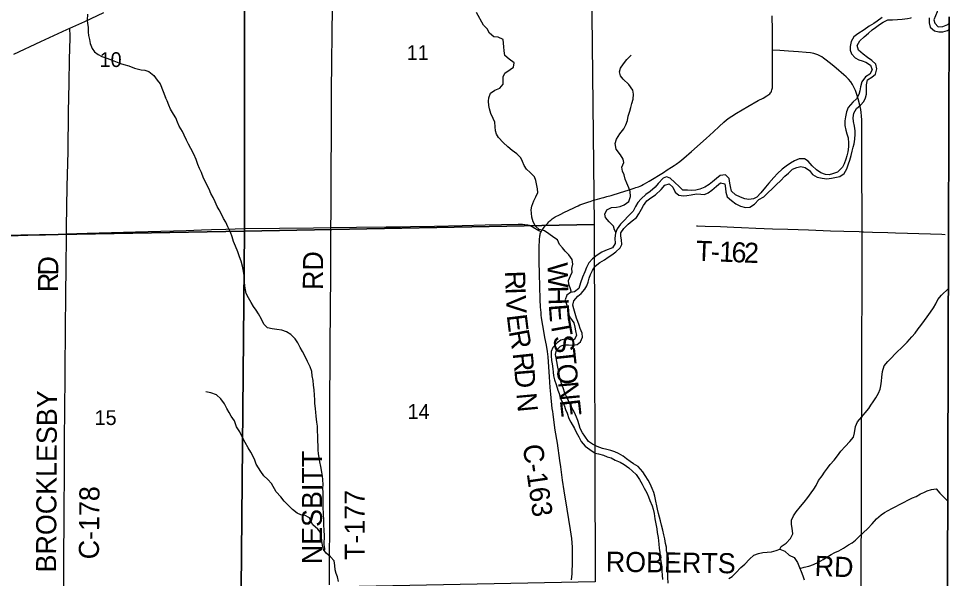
# Model space of a CAD drawing. Extents: x 1584893 to 1934202, y 663575 to 1091909.
# Drawn here: x 1827514 to 1841405, y 948099 to 956462 of the extents above; entities that cross this region are included whole.
import ezdxf

# ---------------------------------------------------------------- set-up
doc = ezdxf.new("R2010")
doc.units = 0
for name, color, linetype in [('GM_X_Adjacent_County', 7, 'Continuous'), ('GM_X_County', 7, 'Continuous'), ('GM_X_County_Road', 7, 'Continuous'), ('GM_X_County_Road_Text', 7, 'Continuous'), ('GM_X_Major_River', 7, 'Continuous'), ('GM_X_Minor_River', 7, 'Continuous'), ('GM_X_Section', 7, 'Continuous'), ('GM_X_Section_Text', 7, 'Continuous'), ('GM_X_State_Route', 7, 'Continuous'), ('GM_X_Township', 7, 'Continuous'), ('GM_X_Township_Road', 7, 'Continuous'), ('GM_X_Township_Road_Text', 7, 'Continuous')]:
    doc.layers.add(name, color=color, linetype=linetype)

msp = doc.modelspace()

# ---------------------------------------------------------------- linework, layer by layer
at = {"layer": 'GM_X_Adjacent_County'}
msp.add_lwpolyline([(1824723, 905333), (1827503, 905733), (1827940, 905796), (1829401, 906007), (1835631, 906848), (1836624, 906977), (1839634, 907367), (1840896, 907530), (1840970, 910855), (1841058, 916141), (1841113, 919520), (1841192, 926713), (1841249, 932050), (1841362, 942439), (1841377, 947941), (1841392, 953202), (1841402, 956488)], dxfattribs=at)
at = {"layer": 'GM_X_County'}
msp.add_lwpolyline([(1841402, 956488), (1841392, 953202), (1841377, 947941), (1841362, 942439), (1841249, 932050), (1841192, 926713), (1841113, 919520), (1841058, 916141), (1840970, 910855), (1840896, 907530), (1839634, 907367), (1836624, 906977), (1835631, 906848), (1829401, 906007), (1827940, 905796), (1827503, 905733), (1824723, 905333)], dxfattribs=at)
at = {"layer": 'GM_X_County_Road'}
for points in [[(1828228, 953245), (1828229, 953346), (1828241, 953954), (1828253, 954479), (1828261, 955070), (1828269, 955497), (1828276, 955858), (1828282, 956170), (1828282, 956252), (1828281, 956268), (1828278, 956318)], [(1836249, 953792), (1836294, 953805), (1836358, 953822), (1836499, 953864), (1836609, 953898), (1836703, 953928), (1836728, 953937), (1836765, 953950), (1836788, 953960), (1836811, 953970), (1836833, 953982), (1836854, 953992), (1836925, 954034), (1837138, 954165), (1837195, 954202), (1837256, 954241), (1837296, 954266), (1837327, 954287), (1837380, 954327), (1837444, 954378), (1837555, 954475), (1837777, 954670), (1837886, 954770), (1837969, 954849), (1838041, 954916), (1838078, 954948), (1838117, 954978), (1838157, 955006), (1838226, 955049), (1838396, 955148), (1838553, 955237), (1838625, 955276), (1838682, 955309), (1838710, 955327), (1838723, 955338), (1838734, 955351), (1838744, 955365), (1838752, 955380), (1838757, 955396), (1838761, 955412), (1838764, 955428), (1838766, 955462), (1838767, 955511), (1838764, 955872), (1838764, 955990)], [(1836025, 953726), (1836043, 953732), (1836096, 953748), (1836153, 953765), (1836221, 953784), (1836249, 953792)], [(1835311, 953278), (1835327, 953305), (1835337, 953318), (1835357, 953344), (1835378, 953369), (1835410, 953406), (1835428, 953424), (1835444, 953441), (1835455, 953451), (1835468, 953463), (1835479, 953472), (1835494, 953482), (1835507, 953491), (1835522, 953499), (1835541, 953510), (1835565, 953522), (1835607, 953543), (1835652, 953564), (1835727, 953601), (1835801, 953637)], [(1835801, 953637), (1835830, 953652), (1835865, 953667), (1835890, 953678), (1835921, 953690), (1835950, 953701), (1836025, 953726)], [(1828228, 953245), (1828539, 953255), (1829260, 953275), (1830015, 953299), (1830244, 953307), (1830392, 953312), (1830605, 953318), (1830884, 953326), (1831409, 953333), (1831917, 953337), (1832163, 953340), (1832176, 953341)], [(1832176, 953341), (1832557, 953347), (1833000, 953351), (1833213, 953352), (1833361, 953354), (1833722, 953361), (1834132, 953371), (1834476, 953381), (1834722, 953387), (1834968, 953391), (1835034, 953389), (1835067, 953387), (1835100, 953382), (1835116, 953379), (1835132, 953374), (1835163, 953363), (1835193, 953348), (1835278, 953298), (1835311, 953278)], [(1822992, 953119), (1822992, 953119), (1823914, 953133), (1824325, 953139), (1824882, 953146), (1825456, 953155), (1825670, 953159), (1826096, 953172), (1826637, 953191), (1827063, 953206), (1827653, 953225), (1827916, 953234), (1828145, 953242), (1828228, 953245)], [(1828190, 947877), (1828189, 947911), (1828188, 947994), (1828190, 948453), (1828194, 948946), (1828195, 949159), (1828199, 949636), (1828200, 949964), (1828200, 950194), (1828202, 950604), (1828208, 951130), (1828210, 951376), (1828213, 951655), (1828215, 951918), (1828218, 952246), (1828223, 952837), (1828227, 953116), (1828228, 953245)], [(1835767, 948077), (1835775, 948170), (1835779, 948350), (1835782, 948498), (1835782, 948564), (1835777, 948629), (1835769, 948695), (1835759, 948758), (1835749, 948824), (1835700, 949132), (1835657, 949407), (1835633, 949569), (1835605, 949764), (1835591, 949861), (1835555, 950121), (1835524, 950316), (1835497, 950510), (1835491, 950551), (1835485, 950592), (1835479, 950640), (1835456, 950852), (1835447, 950949), (1835437, 951111), (1835428, 951260), (1835415, 951407), (1835406, 951489), (1835390, 951586), (1835370, 951699), (1835353, 951792), (1835339, 951877), (1835320, 951990), (1835315, 952031), (1835311, 952071), (1835308, 952110), (1835304, 952152), (1835300, 952267), (1835294, 952464), (1835289, 952644), (1835285, 952840), (1835285, 952972), (1835285, 953053), (1835288, 953152), (1835289, 953174), (1835291, 953200), (1835293, 953215), (1835296, 953232), (1835300, 953248), (1835305, 953263), (1835311, 953278)]]:
    msp.add_lwpolyline(points, dxfattribs=at)
at = {"layer": 'GM_X_Major_River'}
for points in [[(1840400, 956478), (1840327, 956425), (1840276, 956390), (1840210, 956349), (1840133, 956296), (1840038, 956237), (1839979, 956190), (1839938, 956118), (1839923, 956046), (1839922, 955990), (1839942, 955936), (1840001, 955875), (1840053, 955848), (1840105, 955829), (1840160, 955809), (1840230, 955768), (1840255, 955699), (1840216, 955630), (1840153, 955594), (1840100, 955517), (1840081, 955441), (1840067, 955385), (1840056, 955329), (1840019, 955262), (1839966, 955212), (1839895, 955133), (1839870, 955071), (1839853, 954997), (1839844, 954935), (1839847, 954867), (1839860, 954797), (1839877, 954743), (1839893, 954680), (1839900, 954602), (1839897, 954548), (1839888, 954474), (1839875, 954414), (1839858, 954360), (1839835, 954295), (1839809, 954243), (1839735, 954170), (1839663, 954141), (1839613, 954127), (1839557, 954132), (1839489, 954159), (1839423, 954202), (1839356, 954263), (1839297, 954330), (1839243, 954365), (1839165, 954368), (1839095, 954339), (1839036, 954301), (1838969, 954260), (1838909, 954215), (1838840, 954150), (1838783, 954090), (1838711, 954003), (1838659, 953944), (1838593, 953859), (1838530, 953793), (1838480, 953768), (1838414, 953761), (1838352, 953772), (1838286, 953793), (1838212, 953828), (1838151, 953885), (1838138, 953953), (1838128, 954003), (1838119, 954073), (1838062, 954126), (1837986, 954119), (1837931, 954072), (1837872, 954023), (1837822, 953985), (1837753, 953946), (1837680, 953913), (1837620, 953900), (1837552, 953895), (1837498, 953897), (1837428, 953900), (1837372, 953953), (1837309, 954016), (1837236, 954079), (1837184, 954098), (1837132, 954079), (1837059, 954001), (1837014, 953946), (1836939, 953881), (1836876, 953834), (1836805, 953772), (1836754, 953715), (1836721, 953653), (1836686, 953584), (1836613, 953509), (1836552, 953447), (1836497, 953392), (1836448, 953321), (1836421, 953257), (1836410, 953183), (1836419, 953101), (1836376, 953037)], [(1836492, 953036), (1836519, 953089), (1836512, 953157), (1836501, 953212), (1836504, 953264), (1836545, 953325), (1836609, 953389), (1836672, 953440), (1836735, 953493), (1836772, 953545), (1836809, 953614), (1836838, 953672), (1836889, 953739), (1836951, 953783), (1837018, 953830), (1837103, 953909), (1837158, 953972), (1837225, 953995), (1837278, 953942), (1837315, 953870), (1837369, 953825), (1837437, 953816), (1837487, 953821), (1837551, 953829), (1837629, 953842), (1837697, 953839), (1837748, 953836), (1837804, 953857), (1837859, 953897), (1837929, 953958), (1837988, 954011), (1838052, 953992), (1838063, 953924), (1838067, 953870), (1838090, 953801), (1838153, 953746), (1838220, 953697), (1838290, 953662), (1838360, 953639), (1838428, 953646), (1838495, 953690), (1838562, 953759), (1838635, 953802), (1838704, 953867), (1838756, 953912), (1838823, 953984), (1838884, 954041), (1838951, 954106), (1839002, 954154), (1839063, 954213), (1839129, 954240), (1839188, 954253), (1839254, 954238), (1839315, 954195), (1839360, 954133), (1839434, 954094), (1839504, 954077), (1839574, 954070), (1839644, 954077), (1839696, 954086), (1839771, 954103), (1839837, 954148), (1839874, 954220), (1839901, 954292), (1839918, 954348), (1839939, 954419), (1839956, 954483), (1839971, 954541), (1839982, 954593), (1839993, 954663), (1839998, 954735), (1839998, 954787), (1839989, 954855), (1839972, 954926), (1839969, 954982), (1839980, 955050), (1840017, 955121), (1840078, 955167), (1840130, 955226), (1840153, 955280), (1840166, 955334), (1840169, 955386), (1840168, 955474), (1840185, 955548), (1840250, 955585), (1840304, 955632), (1840323, 955712), (1840306, 955781), (1840247, 955835), (1840181, 955882), (1840118, 955931), (1840047, 955990), (1840030, 956059), (1840071, 956132), (1840132, 956192), (1840198, 956247), (1840251, 956294), (1840304, 956329), (1840362, 956375), (1840415, 956410), (1840487, 956444)], [(1840487, 956444), (1840558, 956444), (1840632, 956451), (1840698, 956454), (1840778, 956463), (1840833, 956475), (1840834, 956477)], [(1836376, 953037), (1836272, 952998), (1836217, 952971), (1836148, 952928), (1836080, 952871), (1836023, 952812), (1835988, 952744), (1835963, 952680), (1835930, 952602), (1835902, 952517), (1835873, 952431), (1835810, 952378), (1835750, 952371), (1835698, 952331), (1835673, 952259), (1835690, 952195), (1835709, 952127), (1835716, 952054), (1835753, 951988), (1835802, 951919), (1835817, 951851), (1835827, 951799), (1835838, 951728), (1835803, 951663), (1835749, 951665), (1835689, 951680), (1835608, 951659), (1835554, 951620), (1835489, 951551), (1835464, 951489), (1835461, 951425), (1835468, 951353), (1835475, 951303), (1835486, 951232), (1835492, 951178), (1835499, 951124), (1835510, 951064), (1835535, 950995), (1835564, 950913), (1835579, 950862), (1835597, 950808), (1835616, 950752), (1835655, 950685), (1835678, 950621), (1835702, 950566), (1835727, 950490), (1835754, 950435), (1835809, 950339), (1835836, 950286), (1835875, 950213), (1835910, 950147), (1835969, 950076), (1836037, 950025), (1836118, 949972), (1836170, 949959), (1836242, 949938), (1836300, 949917), (1836356, 949899), (1836419, 949868), (1836491, 949835), (1836553, 949802), (1836622, 949749), (1836729, 949651), (1836782, 949576), (1836819, 949508), (1836852, 949447), (1836888, 949379), (1836915, 949320), (1836934, 949264), (1836969, 949185), (1836982, 949133), (1836998, 949069), (1837009, 948990), (1837024, 948916), (1837037, 948840), (1837046, 948786), (1837057, 948711), (1837062, 948659), (1837067, 948609), (1837075, 948551), (1837082, 948485), (1837089, 948430), (1837098, 948352), (1837113, 948268), (1837116, 948208), (1837121, 948150), (1837126, 948081)], [(1837208, 948030), (1837203, 948118), (1837202, 948176), (1837201, 948227), (1837203, 948279), (1837210, 948335), (1837211, 948403), (1837200, 948453), (1837184, 948515), (1837181, 948567), (1837170, 948620), (1837157, 948688), (1837144, 948750), (1837128, 948822), (1837111, 948895), (1837094, 948959), (1837081, 949013), (1837066, 949070), (1837051, 949134), (1837039, 949184), (1837026, 949254), (1837007, 949327), (1836992, 949385), (1836971, 949442), (1836938, 949514), (1836910, 949567), (1836863, 949639), (1836828, 949690), (1836761, 949769), (1836693, 949810), (1836639, 949845), (1836588, 949885), (1836536, 949924), (1836469, 949967), (1836413, 949992), (1836355, 950009), (1836291, 950024), (1836227, 950040), (1836148, 950072), (1836078, 950105), (1836021, 950147), (1835967, 950222), (1835932, 950273), (1835897, 950341), (1835880, 950394), (1835860, 950458), (1835841, 950510), (1835808, 950577), (1835773, 950646), (1835722, 950750), (1835697, 950807), (1835668, 950869), (1835639, 950948), (1835616, 951010), (1835600, 951066), (1835587, 951127), (1835576, 951183), (1835561, 951255), (1835548, 951338), (1835539, 951394), (1835529, 951444), (1835540, 951510), (1835599, 951569), (1835651, 951591), (1835720, 951590), (1835792, 951583), (1835848, 951596), (1835898, 951633), (1835929, 951701), (1835924, 951765), (1835897, 951832), (1835878, 951884), (1835859, 951938), (1835841, 951989), (1835822, 952057), (1835799, 952125), (1835786, 952182), (1835799, 952248), (1835858, 952315), (1835912, 952354), (1835967, 952418), (1835992, 952471), (1836013, 952525), (1836030, 952583), (1836048, 952637), (1836077, 952697), (1836120, 952764), (1836187, 952821), (1836256, 952860), (1836314, 952900), (1836365, 952935), (1836428, 952976), (1836492, 953036)]]:
    msp.add_lwpolyline(points, dxfattribs=at)
at = {"layer": 'GM_X_Minor_River'}
for points in [[(1840949, 956847), (1841019, 956823), (1841082, 956783), (1841155, 956750), (1841206, 956683), (1841225, 956632), (1841223, 956564), (1841173, 956444)], [(1828540, 956527), (1828539, 956441), (1828544, 956388), (1828553, 956332), (1828554, 956262), (1828559, 956210), (1828571, 956150), (1828584, 956088), (1828613, 956017), (1828646, 955967), (1828701, 955928), (1828757, 955897), (1828815, 955876), (1828884, 955851), (1828958, 955822), (1829036, 955793), (1829087, 955777), (1829157, 955756), (1829245, 955722), (1829344, 955699), (1829400, 955690), (1829458, 955671), (1829531, 955612), (1829582, 955544), (1829627, 955489), (1829705, 955284)], [(1835764, 952372), (1835753, 952423), (1835728, 952493), (1835723, 952549), (1835752, 952617), (1835774, 952673), (1835773, 952727), (1835786, 952795), (1835775, 952865), (1835728, 952934), (1835672, 952987), (1835633, 953039), (1835588, 953090), (1835555, 953158), (1835503, 953193), (1835426, 953248), (1835362, 953293), (1835282, 953314), (1835229, 953359), (1835194, 953426), (1835174, 953496), (1835169, 953554), (1835164, 953604), (1835173, 953662), (1835202, 953742), (1835233, 953798), (1835264, 953865), (1835258, 953920), (1835247, 953970), (1835232, 954046), (1835215, 954100), (1835147, 954161), (1835096, 954212), (1835057, 954269), (1835034, 954329), (1835008, 954380), (1834949, 954441), (1834881, 954490), (1834814, 954548), (1834745, 954610), (1834678, 954685), (1834648, 954735), (1834633, 954785), (1834626, 954845), (1834619, 954914), (1834597, 954970), (1834562, 955047), (1834541, 955113), (1834534, 955163), (1834529, 955229), (1834532, 955281), (1834557, 955347), (1834623, 955392), (1834694, 955425), (1834747, 955485), (1834745, 955541), (1834748, 955591), (1834769, 955645), (1834848, 955700), (1834898, 955735), (1834911, 955801), (1834834, 955856), (1834771, 955911), (1834761, 955979), (1834756, 956042), (1834753, 956096), (1834748, 956150), (1834670, 956183), (1834604, 956190), (1834543, 956247), (1834505, 956307), (1834450, 956366), (1834348, 956553)], [(1841101, 956473), (1841102, 956399), (1841117, 956332), (1841181, 956282), (1841246, 956265), (1841307, 956266), (1841377, 956287), (1841405, 956306)], [(1841173, 956444), (1841190, 956394), (1841239, 956339), (1841306, 956342), (1841380, 956375), (1841405, 956398)], [(1836429, 953274), (1836406, 953307), (1836391, 953361), (1836326, 953426), (1836272, 953489), (1836265, 953541), (1836294, 953605), (1836364, 953640), (1836437, 953645), (1836491, 953655), (1836553, 953678), (1836622, 953731), (1836645, 953805), (1836642, 953881), (1836621, 953935), (1836592, 954002), (1836567, 954062), (1836551, 954126), (1836526, 954185), (1836519, 954243), (1836548, 954313), (1836535, 954363), (1836495, 954426), (1836434, 954513), (1836418, 954595), (1836436, 954659), (1836488, 954740), (1836545, 954814), (1836576, 954875), (1836599, 954941), (1836613, 955007), (1836634, 955081), (1836651, 955133), (1836666, 955195), (1836685, 955260), (1836692, 955334), (1836679, 955395), (1836620, 955476), (1836537, 955555), (1836495, 955608), (1836484, 955666), (1836499, 955722), (1836542, 955787), (1836591, 955849), (1836656, 955916)], [(1832080, 948505), (1832086, 948542), (1832075, 948608), (1832077, 948734), (1832074, 948822), (1832071, 948901), (1832068, 948975), (1832063, 949055), (1832061, 949175), (1832058, 949261), (1832059, 949384), (1832056, 949448), (1832057, 949498), (1832056, 949576), (1832051, 949626), (1832039, 949686), (1832025, 949769), (1832008, 949841), (1832000, 949901), (1831991, 949963), (1831986, 950017), (1831983, 950074), (1831982, 950160), (1831979, 950224), (1831976, 950306), (1831973, 950372), (1831967, 950432), (1831957, 950523), (1831951, 950581), (1831946, 950633), (1831937, 950719), (1831934, 950769), (1831929, 950838), (1831924, 950916), (1831917, 950988), (1831910, 951054), (1831897, 951124), (1831890, 951191), (1831864, 951259), (1831827, 951338), (1831787, 951422), (1831751, 951487), (1831718, 951551), (1831681, 951618), (1831644, 951677), (1831579, 951742), (1831511, 951785), (1831441, 951810), (1831369, 951819), (1831297, 951830), (1831227, 951845), (1831174, 951897), (1831137, 951970), (1831094, 952051), (1831059, 952109), (1831021, 952162), (1830984, 952220), (1830943, 952289), (1830912, 952356), (1830900, 952408), (1830891, 952464), (1830884, 952536), (1830885, 952596), (1830872, 952689), (1830855, 952765), (1830836, 952841), (1830813, 952902), (1830784, 952976), (1830749, 953065), (1830722, 953133), (1830701, 953200), (1830676, 953270), (1830637, 953353), (1830606, 953423), (1830570, 953474), (1830545, 953530), (1830508, 953603), (1830479, 953657), (1830449, 953724), (1830416, 953790), (1830385, 953849), (1830356, 953913), (1830276, 954079), (1830245, 954161), (1830214, 954222), (1830189, 954284), (1830164, 954357), (1830127, 954437), (1830086, 954520), (1830050, 954585), (1830021, 954645), (1829986, 954720), (1829959, 954774), (1829908, 954857), (1829887, 954915), (1829859, 954978), (1829824, 955036), (1829781, 955111), (1829756, 955167), (1829731, 955234), (1829705, 955284)], [(1838876, 948538), (1838896, 948576), (1838967, 948627), (1839036, 948697), (1839071, 948764), (1839058, 948849), (1839051, 948903), (1839050, 948969), (1839077, 949035), (1839116, 949096), (1839183, 949175), (1839236, 949239), (1839293, 949306), (1839344, 949376), (1839383, 949433), (1839417, 949489), (1839454, 949560), (1839504, 949632), (1839542, 949685), (1839587, 949747), (1839628, 949800), (1839685, 949866), (1839734, 949931), (1839785, 949999), (1839850, 950068), (1839921, 950147), (1839972, 950210), (1839989, 950274), (1840006, 950368), (1840035, 950436), (1840098, 950511), (1840149, 950575), (1840202, 950636), (1840235, 950688), (1840266, 950739), (1840305, 950799), (1840346, 950868), (1840373, 950926), (1840383, 950978), (1840390, 951046), (1840395, 951108), (1840406, 951188), (1840433, 951274), (1840484, 951339), (1840535, 951391), (1840594, 951452), (1840718, 951572), (1840773, 951630), (1840844, 951709), (1840893, 951764), (1840940, 951828), (1840977, 951879), (1841034, 951953), (1841074, 952006), (1841125, 952076), (1841168, 952143), (1841201, 952203), (1841234, 952265), (1841285, 952330), (1841394, 952432)], [(1832288, 948054), (1832271, 948121), (1832251, 948173), (1832240, 948225), (1832235, 948293), (1832226, 948360), (1832171, 948421), (1832103, 948474), (1832062, 948530), (1832049, 948594), (1832040, 948657), (1832034, 948719), (1832019, 948783), (1831980, 948834), (1831907, 948901), (1831873, 948953), (1831854, 949004), (1831782, 949045), (1831726, 949047), (1831673, 949072), (1831601, 949129), (1831550, 949176), (1831479, 949255), (1831427, 949316), (1831358, 949395), (1831288, 949516), (1831233, 949577), (1831173, 949632), (1831130, 949698), (1831093, 949751), (1831059, 949808), (1831038, 949868), (1831013, 949920), (1830980, 949987), (1830940, 950048), (1830896, 950128), (1830854, 950203), (1830816, 950290), (1830768, 950362), (1830736, 950451), (1830684, 950522), (1830655, 950576), (1830622, 950637), (1830589, 950705), (1830534, 950780), (1830466, 950841), (1830381, 950874), (1830309, 950887)], [(1839175, 948246), (1839237, 948269), (1839305, 948284), (1839379, 948307), (1839450, 948340), (1839523, 948380), (1839577, 948417), (1839640, 948456), (1839694, 948485), (1839753, 948513), (1839825, 948552), (1839898, 948599), (1839953, 948630), (1840005, 948670), (1840066, 948729), (1840117, 948780), (1840186, 948847), (1840251, 948915), (1840318, 948990), (1840385, 949047), (1840436, 949082), (1840492, 949112), (1840545, 949145), (1840597, 949170), (1840670, 949207), (1840722, 949235), (1840793, 949272), (1840853, 949303), (1840908, 949324), (1840972, 949362), (1841025, 949383), (1841075, 949406), (1841138, 949427), (1841210, 949438), (1841263, 949372), (1841385, 949247)], [(1838112, 948098), (1838165, 948129), (1838216, 948185), (1838291, 948260), (1838352, 948313), (1838423, 948388), (1838488, 948448), (1838554, 948473), (1838620, 948486), (1838685, 948493), (1838749, 948498), (1838819, 948517), (1838876, 948538), (1838947, 948505), (1839015, 948446), (1839090, 948413), (1839139, 948339), (1839168, 948260), (1839194, 948202), (1839217, 948137), (1839236, 948077)]]:
    msp.add_lwpolyline(points, dxfattribs=at)
at = {"layer": 'GM_X_Section'}
for points in [[(1830887, 958663), (1836044, 958759), (1836103, 953387), (1830886, 953288)], [(1825675, 958497), (1830887, 958663), (1830886, 953288), (1825595, 953192)], [(1830886, 953288), (1836103, 953387), (1836120, 948050), (1830834, 947945)], [(1825595, 953192), (1830886, 953288), (1830834, 947945), (1825540, 947842)]]:
    msp.add_lwpolyline(points, close=True, dxfattribs=at)
at = {"layer": 'GM_X_State_Route'}
for points in [[(1827442, 955933), (1827845, 956118), (1828232, 956297), (1828278, 956318), (1828501, 956420), (1828784, 956551)], [(1839716, 955720), (1839655, 955771), (1839566, 955843), (1839527, 955873), (1839500, 955891), (1839472, 955906), (1839442, 955920), (1839412, 955931), (1839381, 955940), (1839333, 955950), (1839268, 955958), (1839154, 955968), (1839006, 955978), (1838875, 955985), (1838764, 955990), (1838764, 956291), (1838761, 956505)], [(1840096, 954768), (1840096, 954796), (1840096, 954944), (1840094, 955009), (1840090, 955058), (1840082, 955106), (1840068, 955170), (1840043, 955265), (1840020, 955344), (1840003, 955390), (1839991, 955420), (1839976, 955449), (1839960, 955477), (1839932, 955517), (1839901, 955555), (1839867, 955590), (1839831, 955623), (1839716, 955720)], [(1840086, 947984), (1840087, 948149), (1840088, 948527), (1840091, 948872), (1840091, 949101), (1840092, 949282), (1840092, 949561), (1840093, 949988), (1840094, 950218), (1840094, 950398), (1840096, 950595), (1840096, 950973), (1840098, 951219), (1840098, 951498), (1840098, 951629), (1840100, 951859), (1840101, 952187), (1840101, 952368), (1840101, 952466), (1840101, 952712), (1840102, 952877), (1840103, 953156), (1840103, 953278), (1840102, 953418), (1840101, 953746), (1840100, 953960), (1840100, 954042), (1840100, 954157), (1840100, 954320), (1840099, 954452), (1840098, 954599), (1840096, 954768)]]:
    msp.add_lwpolyline(points, dxfattribs=at)
at = {"layer": 'GM_X_Township'}
msp.add_lwpolyline([(1841402, 956488), (1841392, 953202), (1841377, 947941), (1841362, 942439), (1841249, 932050), (1840028, 932073), (1836047, 932032), (1830742, 931948), (1828867, 931882), (1825463, 931824), (1818808, 931710), (1816203, 931710), (1814867, 931692), (1810616, 931766)], dxfattribs=at)
at = {"layer": 'GM_X_Township_Road'}
for points in [[(1832176, 953341), (1832176, 953372), (1832177, 953536), (1832179, 953913), (1832178, 954094), (1832181, 954356), (1832182, 954570), (1832184, 954799), (1832185, 955078), (1832184, 955226), (1832186, 955406), (1832190, 955784), (1832193, 956259), (1832197, 956604), (1832201, 957408), (1832203, 957785), (1832203, 957998), (1832202, 958071), (1832202, 958091), (1832203, 958111), (1832205, 958130), (1832205, 958130)], [(1832156, 948002), (1832156, 948040), (1832156, 948056), (1832156, 948253), (1832156, 948467), (1832159, 948795), (1832161, 949123), (1832161, 949500), (1832159, 949763), (1832158, 949976), (1832159, 950189), (1832159, 950419), (1832157, 950616), (1832158, 950731), (1832160, 950911), (1832162, 951206), (1832164, 951485), (1832169, 952207), (1832173, 952552), (1832173, 952798), (1832176, 953060), (1832175, 953208), (1832176, 953339), (1832176, 953341)], [(1837632, 953367), (1837647, 953368), (1837761, 953362), (1837991, 953354), (1838188, 953345), (1838303, 953340), (1838516, 953331), (1838763, 953323), (1838993, 953316), (1839304, 953305), (1839633, 953293), (1839830, 953287), (1840060, 953281), (1840103, 953278)], [(1840103, 953278), (1840125, 953277), (1840256, 953274), (1840486, 953266), (1840601, 953263), (1840782, 953258), (1841291, 953240), (1841344, 953239)]]:
    msp.add_lwpolyline(points, dxfattribs=at)

# ---------------------------------------------------------------- texts
at = {"layer": 'GM_X_County_Road_Text'}
for s, rotation, p in [('D', 89.2058, (1828104, 952622)), ('W', 271.688, (1835406, 952814)), ('R', 89.9883, (1828104, 952377)), ('R', 272.0339, (1834772, 952691)), ('I', 272.0589, (1834781, 952444)), ('H', 271.7204, (1835416, 952467)), ('V', 272.2709, (1834786, 952320)), ('E', 274.4434, (1835425, 952187)), ('E', 276.9534, (1834798, 952030)), ('T', 280.1904, (1835447, 951931)), ('R', 280.2728, (1834828, 951789)), ('S', 279.3014, (1835486, 951711)), ('T', 276.1358, (1835518, 951516)), ('R', 276.1355, (1834886, 951461)), ('O', 275.0846, (1835542, 951294)), ('D', 274.7993, (1834912, 951218)), ('N', 275.127, (1835566, 951031)), ('BROCKLESBY', 89.6885, (1828073, 948188)), ('N', 275.2805, (1834942, 950860)), ('E', 276.3735, (1835590, 950761)), ('C-163', 278.2102, (1835036, 950084)), ('C-178', 89.4553, (1828712, 948383))]:
    msp.add_text(s, height=300, rotation=rotation, dxfattribs=at).set_placement(p)
at = {"layer": 'GM_X_Section_Text'}
for s, p in [('10', (1828723, 955739)), ('11', (1833306, 955844)), ('14', (1833319, 950482)), ('15', (1828648, 950391))]:
    msp.add_text(s, height=221, rotation=0, dxfattribs=at).set_placement(p)
at = {"layer": 'GM_X_Township_Road_Text'}
for s, rotation, p in [('T', 357.7109, (1837617, 952846)), ('1', 357.7155, (1837964, 952833)), ('6', 357.7466, (1838149, 952825)), ('2', 357.9278, (1838335, 952818)), ('RD', 89.5068, (1832055, 952407)), ('-', 357.7092, (1837841, 952837)), ('NESBITT', 90, (1832042, 948311)), ('T-177', 90, (1832680, 948373)), ('ROBERTS', 359.2384, (1836275, 948200)), ('RD', 357.5333, (1839389, 948139))]:
    msp.add_text(s, height=300, rotation=rotation, dxfattribs=at).set_placement(p)

doc.saveas('drawing.dxf')
